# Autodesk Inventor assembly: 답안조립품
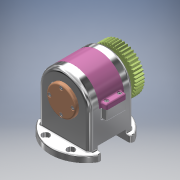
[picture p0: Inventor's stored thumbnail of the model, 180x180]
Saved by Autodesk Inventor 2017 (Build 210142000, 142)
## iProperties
Part Number: 답안조립품
Material: 일반
Document SubType Name: Assembly
Designer: MRC
Author: MRC
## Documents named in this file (21)
- C:\Users\MRC\Desktop\740804V1010\답안조립품.iam
- C:\Users\MRC\Desktop\740804V1010\본체.ipt
- C:\Users\MRC\Desktop\740804V1010\오일레스 부시 20 15.ipt
- C:\Users\MRC\Desktop\740804V1010\부시 커버.ipt
- C:\Users\MRC\Desktop\740804V1010\육각 소켓 머리 볼트 M4x10.ipt
- C:\Users\MRC\Desktop\740804V1010\링크.ipt
- C:\Users\MRC\Desktop\740804V1010\펀치.ipt
- C:\Users\MRC\Desktop\740804V1010\핀.ipt
- C:\Users\MRC\Desktop\740804V1010\E형 멈춤링 10-8.ipt
- C:\Users\MRC\Desktop\740804V1010\깊은 홈 볼 베어링 6904.ipt
- C:\Users\MRC\Desktop\740804V1010\칼라.ipt
- C:\Users\MRC\Desktop\740804V1010\편심축.ipt
- C:\Users\MRC\Desktop\740804V1010\뒷커버.ipt
- C:\Users\MRC\Desktop\740804V1010\오일실 20 32 5.ipt
- C:\Users\MRC\Desktop\740804V1010\앞커버.ipt
- C:\Users\MRC\Desktop\740804V1010\평행키 5x5x12.ipt
- C:\Users\MRC\Desktop\740804V1010\스퍼 기어.ipt
- C:\Users\MRC\Desktop\740804V1010\평와셔 M10.ipt
- C:\Users\MRC\Desktop\740804V1010\스프링 와셔 M10.ipt
- C:\Users\MRC\Desktop\740804V1010\육각 너트 M10x1.ipt
- C:\Users\MRC\Desktop\740804V1010\윗커버.ipt
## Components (2 placed, 2 different names)
1. 핀:1
2. E형 멈춤링 10-8:1
